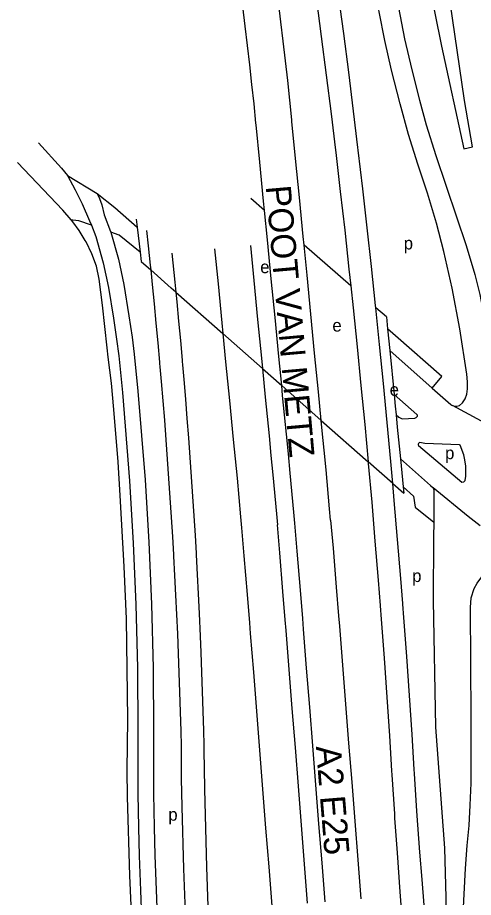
# Model space of a CAD drawing. Extents: x 157699 to 159683, y 381451 to 383293.
# Drawn here: x 157720.7 to 157866.4, y 382131.3 to 382412.9 of the extents above; entities that cross this region are included whole.
import ezdxf

# ---------------------------------------------------------------- set-up
doc = ezdxf.new("R2010")
doc.units = 0
for name, color, linetype in [('BLT_Basislijn', 7, 'Continuous'), ('BLT_Centroide', 7, 'Continuous'), ('BLT_Gemeentegrens', 7, 'Continuous'), ('BLT_Straatnaam_hoofdweg', 7, 'Continuous'), ('BLT_Vlakafsluiter', 7, 'Continuous')]:
    doc.layers.add(name, color=color, linetype=linetype)

msp = doc.modelspace()

# ---------------------------------------------------------------- linework, layer by layer
at = {"layer": 'BLT_Basislijn'}
for p, q in [((157799.65, 382351.16), (157795.29, 382354.97)), ((157758.57, 382348.35), (157758.88, 382345.84)), ((157758.88, 382345.84), (157759.85, 382337.82)), ((157827.23, 382327.06), (157812.29, 382340.11)), ((157759.85, 382337.82), (157760.21, 382334.82)), ((157760.21, 382334.82), (157763.26, 382332.13)), ((157771.26, 382325.06), (157786.33, 382311.76)), ((157838.62, 382317.1), (157835.26, 382320.03)), ((157838.62, 382317.1), (157838.99, 382313.33)), ((157841.54, 382311.08), (157838.99, 382313.33)), ((157838.99, 382313.33), (157839.68, 382306.33)), ((157839.68, 382306.33), (157853.29, 382294.34)), ((157839.68, 382306.33), (157841.07, 382292.27)), ((157798.98, 382300.6), (157805.14, 382295.16)), ((157841.07, 382292.27), (157841.44, 382288.5)), ((157841.44, 382288.5), (157841.71, 382285.74)), ((157841.71, 382285.74), (157842.1, 382281.81)), ((157817.79, 382283.99), (157832.77, 382270.77)), ((157842.1, 382281.81), (157843.1, 382271.64)), ((157843.1, 382271.64), (157843.98, 382262.73)), ((157840.67, 382263.8), (157844.18, 382260.7)), ((157843.98, 382262.73), (157844.18, 382260.7)), ((157853.75, 382251.41), (157853.71, 382246.63))]:
    msp.add_line(p, q, dxfattribs=at)
for points in [[(157814.31, 382688.66), (157806.99, 382684.84), (157802.17, 382680.96), (157802.03, 382678.58), (157833.39, 382559.57), (157852.12, 382424.4), (157856.21, 382403.71), (157863.37, 382370.92), (157866.2, 382371.54)], [(157866.2, 382371.54), (157863.56, 382386.33), (157840.74, 382543.08), (157839.7, 382551.81), (157840.08, 382554.13), (157840.98, 382555.96), (157842.28, 382555.94), (157841.59, 382560.09), (157838.61, 382565.98), (157821.37, 382684.05), (157819.38, 382686.74), (157815.85, 382688.1), (157814.31, 382688.66)], [(157807.23, 382481.85), (157807.34, 382481.13), (157809.2, 382468.77), (157809.56, 382466.31), (157811.01, 382456.4), (157812.77, 382444.03), (157814.49, 382431.65), (157816.17, 382419.26), (157816.28, 382418.45), (157817.8, 382406.87), (157819.39, 382394.48), (157820.93, 382382.07), (157822.33, 382370.51), (157822.43, 382369.67), (157823.88, 382357.25), (157825.29, 382344.83), (157826.66, 382332.41), (157827.23, 382327.06)], [(157799.65, 382351.16), (157799.36, 382354.19), (157798.14, 382366.63), (157796.97, 382378.53), (157796.92, 382379.07), (157796.29, 382385.3), (157795.64, 382391.53), (157794.95, 382397.75), (157794.24, 382403.98), (157793.5, 382410.2), (157792.74, 382416.41), (157791.94, 382422.62), (157791.12, 382428.83), (157790.27, 382435.04), (157789.4, 382441.24), (157788.49, 382447.43), (157787.56, 382453.63), (157786.63, 382459.63), (157785.67, 382465.64), (157785.61, 382466), (157783.62, 382478.34), (157783.39, 382479.71)], [(157812.29, 382340.11), (157812.02, 382342.87), (157810.8, 382355.31), (157809.58, 382367.75), (157808.42, 382379.65), (157808.36, 382380.2), (157807.73, 382386.48), (157807.07, 382392.76), (157806.38, 382399.03), (157805.66, 382405.31), (157804.92, 382411.58), (157804.15, 382417.84), (157803.35, 382424.11), (157802.52, 382430.37), (157801.66, 382436.62), (157800.78, 382442.87), (157799.87, 382449.12), (157798.93, 382455.36), (157797.99, 382461.42), (157797.02, 382467.47), (157796.96, 382467.83), (157794.97, 382480.17), (157794.88, 382480.74)], [(157859.77, 382288.75), (157860.35, 382288.55), (157861.15, 382288.53), (157861.96, 382288.73), (157862.91, 382289.57), (157863.78, 382290.94), (157864.3, 382292.34), (157864.51, 382294.07), (157864.52, 382296.33), (157864.35, 382298.77), (157862.1, 382313.28), (157859.69, 382326.35), (157857.03, 382338.03), (157854.64, 382347.07), (157851.82, 382356.67), (157848.72, 382366.03), (157845.72, 382375.52), (157842.98, 382385.26), (157840.24, 382396.11), (157838.14, 382405.55), (157836.33, 382414.77), (157834.63, 382425.07)], [(157835.26, 382320.03), (157835.19, 382320.74), (157833.87, 382333.19), (157832.5, 382345.64), (157831.09, 382358.08), (157829.63, 382370.52), (157829.53, 382371.37), (157828.13, 382382.96), (157826.58, 382395.38), (157824.99, 382407.81), (157823.35, 382420.22)], [(157842.49, 382416.11), (157844.46, 382406.06), (157846.72, 382396.15), (157849.16, 382386.42), (157851.39, 382378.58), (157854.48, 382368.73), (157861.08, 382349.18), (157864.09, 382339.92), (157866.95, 382330.66), (157868.51, 382324.33), (157870.3, 382314.78), (157872.07, 382302.05), (157872.93, 382294.52), (157873.7, 382289.49), (157874.36, 382286.95), (157875.34, 382284.62), (157876.6, 382282.47), (157879.28, 382279.71), (157880.94, 382277.93), (157882.56, 382276.42)], [(157727.34, 382372.81), (157727.38, 382372.77), (157734.78, 382364.74), (157736.6, 382362.32)], [(157736.6, 382362.32), (157739.15, 382357.73), (157741.34, 382353.31), (157743.73, 382347.87), (157744.3, 382346.42)], [(157746.17, 382356.65), (157751.77, 382352.09), (157758.88, 382345.84)], [(157746.17, 382356.65), (157746.89, 382355.05), (157747.58, 382352.99), (157748.35, 382349.79), (157750.44, 382344.43), (157750.5, 382344.24)], [(157805.14, 382295.16), (157804.23, 382304.43), (157803.02, 382316.87), (157801.8, 382329.31), (157800.58, 382341.75), (157799.65, 382351.16)], [(157744.3, 382346.42), (157740.24, 382347.84), (157738.35, 382348.08), (157737.86, 382348.14)], [(157744.3, 382346.42), (157745.7, 382342.83), (157748.08, 382334.44), (157749.71, 382326.53), (157751.34, 382316.7), (157752.35, 382309.98), (157753.05, 382304.62), (157754.21, 382292.92), (157756.47, 382264.66), (157757.7, 382244.71), (157758.52, 382225.07), (157759.04, 382204.67), (157759.16, 382184.49), (157759.15, 382164.47), (157759.33, 382153.76), (157759.59, 382144.6), (157759.99, 382133.6), (157760.34, 382124.84)], [(157750.5, 382344.24), (157752.94, 382335.63), (157754.63, 382327.44), (157756.28, 382317.48), (157757.3, 382310.67), (157758.01, 382305.19), (157759.19, 382293.36), (157761.46, 382265.01), (157762.69, 382244.97), (157763.52, 382225.23), (157764.04, 382204.75), (157764.16, 382184.51), (157764.15, 382164.51), (157764.33, 382153.87), (157764.58, 382144.76), (157764.99, 382133.79), (157765.34, 382125.1), (157766.55, 382105.53), (157767.26, 382095.3), (157769.13, 382074.95), (157771.51, 382054.04), (157775.38, 382026.18), (157778.6, 382006.44), (157784.9, 381970.44)], [(157759.85, 382337.82), (157753.17, 382343.31), (157750.5, 382344.24)], [(157761.9, 382344.81), (157762.45, 382339.84), (157763.1, 382333.65), (157763.26, 382332.13)], [(157783.68, 382338.84), (157784.78, 382327.64), (157786, 382315.2), (157786.33, 382311.76)], [(157795.13, 382339.95), (157796.22, 382328.76), (157797.44, 382316.32), (157798.66, 382303.88), (157798.98, 382300.6)], [(157817.79, 382283.99), (157816.9, 382293.11), (157815.68, 382305.55), (157814.46, 382317.99), (157813.24, 382330.43), (157812.29, 382340.11)], [(157769.98, 382337.51), (157770.31, 382334.4), (157770.95, 382328.18), (157771.26, 382325.06)], [(157763.26, 382332.13), (157763.74, 382327.45), (157764.36, 382321.26), (157764.95, 382315.06), (157765.53, 382308.86), (157766.09, 382302.65), (157766.12, 382302.23), (157766.21, 382301.18), (157766.62, 382296.45), (157767.14, 382290.24), (157767.63, 382284.03), (157768.11, 382277.82), (157768.57, 382271.61), (157769, 382265.4), (157769.42, 382259.18), (157769.82, 382252.97), (157770.19, 382246.75), (157770.52, 382241.11), (157770.55, 382240.53), (157770.89, 382234.32), (157771.2, 382228.1), (157771.5, 382221.87), (157771.78, 382215.65), (157772.03, 382209.43), (157772.27, 382203.21), (157772.48, 382196.98), (157772.68, 382190.76), (157772.86, 382184.53), (157772.97, 382179.88), (157773.01, 382178.3), (157772.98, 382169.44), (157773.16, 382160.33), (157773.78, 382140.51), (157774.31, 382126.57)], [(157827.23, 382327.06), (157827.98, 382319.98), (157829.26, 382307.55), (157830.49, 382295.11), (157831.68, 382282.67), (157832.77, 382270.77)], [(157771.26, 382325.06), (157771.57, 382321.96), (157772.17, 382315.74), (157772.75, 382309.52), (157773.31, 382303.29), (157773.34, 382302.86), (157773.44, 382301.81), (157773.85, 382297.06), (157774.36, 382290.83), (157774.86, 382284.6), (157775.34, 382278.37), (157775.8, 382272.13), (157776.24, 382265.9), (157776.66, 382259.66), (157777.05, 382253.42), (157777.43, 382247.18), (157777.76, 382241.51), (157777.79, 382240.94), (157778.13, 382234.7), (157778.44, 382228.45), (157778.74, 382222.21), (157779.06, 382214.97)], [(157840.67, 382263.8), (157840.05, 382270.87), (157838.9, 382283.35), (157837.71, 382295.81), (157836.47, 382308.28), (157835.26, 382320.03)], [(157786.33, 382311.76), (157787.22, 382302.76), (157788.44, 382290.32), (157789.66, 382277.88), (157790.27, 382271.64), (157790.86, 382265.48), (157791.99, 382253.12), (157792.3, 382249.6)], [(157853.29, 382294.34), (157856.3, 382298.08), (157841.54, 382311.08)], [(157798.98, 382300.6), (157799.88, 382291.44), (157801.1, 382279), (157801.71, 382272.77), (157802.31, 382266.57), (157803.45, 382254.14), (157803.76, 382250.6)], [(157809.34, 382251.08), (157809.03, 382254.63), (157807.88, 382267.1), (157807.28, 382273.31), (157806.67, 382279.55), (157805.45, 382291.99), (157805.14, 382295.16)], [(157853.29, 382294.34), (157858.38, 382289.85), (157859.21, 382289.1), (157859.49, 382288.89), (157859.77, 382288.75)], [(157841.71, 382285.74), (157842.57, 382284.98), (157843.62, 382284.48), (157847.75, 382284.75), (157848.12, 382284.91), (157848.41, 382285.1), (157848.54, 382285.36), (157848.53, 382285.65), (157848.38, 382285.85), (157841.07, 382292.27)], [(157820.8, 382252.08), (157820.48, 382255.65), (157819.33, 382268.18), (157818.73, 382274.43), (157818.12, 382280.67), (157817.79, 382283.99)], [(157832.77, 382270.77), (157832.82, 382270.22), (157833.92, 382257.77), (157834.98, 382245.32), (157835.99, 382232.86), (157836.62, 382224.8), (157836.63, 382224.62), (157836.96, 382220.4), (157837.88, 382207.94), (157838.75, 382195.47), (157839.59, 382183), (157840.29, 382171.87), (157840.38, 382170.52), (157841.18, 382158.05), (157841.26, 382156.74), (157842.03, 382145.58), (157842.94, 382133.11), (157843.9, 382120.64)], [(157843.1, 382271.64), (157852.72, 382263.17), (157853.53, 382262.43)], [(157854.01, 382088.97), (157852.13, 382111.04), (157850.07, 382137.09), (157849.3, 382145.82), (157848.34, 382158.92), (157847.61, 382170.98), (157847.53, 382172.31), (157846.82, 382183.47), (157845.99, 382195.97), (157845.11, 382208.46), (157844.18, 382220.95), (157843.86, 382225.17), (157843.85, 382225.36), (157843.22, 382233.44), (157842.2, 382245.92), (157841.15, 382258.4), (157840.67, 382263.8)], [(157843.98, 382262.73), (157847.34, 382259.78), (157847.82, 382256.19), (157853.75, 382251.41)], [(157853.53, 382262.43), (157853.74, 382262.12), (157853.82, 382261.76), (157853.75, 382251.41)], [(157819.03, 382129.96), (157818.05, 382142.42), (157817.06, 382154.88), (157816.08, 382167.34), (157815.09, 382179.8), (157814.11, 382192.26), (157813.12, 382204.72), (157812.14, 382217.18), (157811.87, 382220.56), (157811.14, 382229.65), (157810.11, 382242.12), (157809.34, 382251.08)], [(157820.8, 382252.08), (157821.57, 382243.09), (157822.6, 382230.58), (157823.33, 382221.46), (157823.6, 382218.09), (157824.59, 382205.63), (157825.57, 382193.17), (157826.56, 382180.71), (157827.54, 382168.25), (157828.53, 382155.79), (157829.51, 382143.32), (157830.5, 382130.86)], [(157792.3, 382249.6), (157793.07, 382240.68), (157794.1, 382228.26), (157794.82, 382219.21), (157795.09, 382215.84), (157796.08, 382203.38), (157797.06, 382190.91), (157798.05, 382178.45), (157799.03, 382165.99), (157800.02, 382153.53), (157801, 382141.07), (157801.99, 382128.61)], [(157813.45, 382129.52), (157812.47, 382141.98), (157811.48, 382154.44), (157810.5, 382166.9), (157809.51, 382179.36), (157808.52, 382191.82), (157807.54, 382204.28), (157806.55, 382216.74), (157806.29, 382220.12), (157805.56, 382229.2), (157804.53, 382241.65), (157803.76, 382250.6)], [(157853.71, 382246.63), (157853.57, 382226.38)], [(157870.06, 381934.31), (157867.05, 381973.8), (157865.68, 381993.87), (157864.55, 382022.12), (157863.4, 382041.04), (157863.08, 382054.8), (157862.87, 382062.83), (157862.77, 382082.25), (157862.74, 382092.84), (157862.8, 382114.69), (157863.2, 382126.22), (157863.95, 382140.63), (157864.47, 382147.95), (157865.05, 382154.36), (157865.43, 382160.91), (157865.68, 382167.86), (157865.71, 382188.66), (157865.51, 382224.16), (157865.78, 382227.21), (157866.65, 382230.22), (157867.7, 382231.89), (157870.66, 382235.92)], [(157853.57, 382226.38), (157854.37, 382185.85), (157857.21, 382147.08), (157857.64, 382131.31), (157857.83, 382121.86), (157857.84, 382115.92)], [(157779.06, 382214.97), (157779.28, 382209.72), (157779.51, 382203.47), (157779.73, 382197.22), (157779.93, 382190.97), (157780.1, 382184.72), (157780.22, 382180.05), (157780.26, 382178.47), (157780.51, 382166.34), (157780.51, 382165.97), (157780.77, 382153.48), (157781.1, 382140.99), (157781.51, 382128.5)]]:
    msp.add_lwpolyline(points, dxfattribs=at)
msp.add_lwpolyline([(157848.89, 382275.99), (157862.8, 382264.27), (157863.35, 382264.3), (157863.86, 382264.77), (157864.04, 382266.13), (157864.02, 382268.14), (157864.01, 382269.32), (157863.7, 382271.32), (157863.44, 382272.98), (157862.2, 382276.03), (157861.95, 382276.2), (157850.96, 382276.58), (157849.83, 382276.79), (157849.34, 382276.87), (157849.15, 382276.81), (157848.91, 382276.63), (157848.83, 382276.39), (157848.8, 382276.15)], close=True, dxfattribs=at)
at = {"layer": 'BLT_Gemeentegrens'}
for points in [[(157737.86, 382348.14), (157735.13, 382351.26), (157720.7, 382366.55)], [(157749.37, 382307.22), (157747.85, 382320.9), (157746.82, 382329.23), (157745.89, 382333.35), (157744.43, 382337.29), (157742.62, 382341.13), (157742.33, 382341.6), (157740.41, 382344.71), (157738.35, 382347.48), (157737.89, 382348.11), (157737.86, 382348.14)], [(157774.52, 381975.12), (157769.41, 382006.76), (157766.75, 382023.87), (157763.24, 382048.83), (157761.3, 382065.53), (157759.11, 382086.81), (157758.79, 382090.22), (157758.94, 382096.45), (157757.81, 382113.2), (157757.32, 382121.56), (157756.54, 382138.36), (157755.86, 382163.54), (157755.77, 382171.94), (157755.9, 382188.37), (157755.78, 382204.45), (157755.47, 382220.5), (157754.8, 382237.26), (157753.48, 382259.91), (157752.84, 382270.77), (157751.46, 382287.51), (157750.73, 382295.87), (157749.7, 382304.21), (157749.37, 382307.22)]]:
    msp.add_lwpolyline(points, dxfattribs=at)
at = {"layer": 'BLT_Vlakafsluiter'}
for p, q in [((157736.6, 382362.32), (157746.17, 382356.65)), ((157769.81, 382326.34), (157763.26, 382332.13)), ((157771.26, 382325.06), (157769.81, 382326.34)), ((157798.98, 382300.6), (157786.33, 382311.76)), ((157817.79, 382283.99), (157805.14, 382295.16)), ((157882.56, 382276.42), (157859.77, 382288.75)), ((157840.67, 382263.8), (157832.77, 382270.77))]:
    msp.add_line(p, q, dxfattribs=at)
msp.add_lwpolyline([(157868.58, 382250.23), (157864.81, 382253.21), (157853.53, 382262.43)], dxfattribs=at)

# ---------------------------------------------------------------- texts
at = {"layer": 'BLT_Centroide'}
for s, p in [('p', (157844.17, 382338.7)), ('e', (157798.28, 382331.1)), ('e', (157821.36, 382312.41)), ('e', (157839.68, 382291.86)), ('p', (157857.39, 382271.57)), ('p', (157846.87, 382232.27)), ('p', (157768.89, 382155.89))]:
    msp.add_text(s, height=4, dxfattribs=at).set_placement(p)
at = {"layer": 'BLT_Straatnaam_hoofdweg'}
for s, rotation, p in [('POOT VAN METZ', 275.0436, (157800.03, 382358.9)), ('A2 E25', 274.6416, (157816.07, 382179.65))]:
    msp.add_text(s, height=8, rotation=rotation, dxfattribs=at).set_placement(p)

doc.saveas('drawing.dxf')
